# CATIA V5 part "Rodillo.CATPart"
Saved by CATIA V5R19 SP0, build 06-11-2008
Part number: Rodillo
Publications: "Plane.1"
Material "Iron": density 7870 kg/m3, Young's modulus 1.2e+11 Pa, Poisson ratio 0.291, thermal expansion 1.21e-05 1/K
Bounding box of the stored display mesh (mm): x -19.05 to 19.05, y -25.4 to 25.4, z -25.215 to 25.215
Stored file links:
  E:\Luis\Dropbox\3DIT\Parking\planos\cat 3 dit park8\Rodillo.CATPart
  E:\Luis\Dropbox\3DIT\Parking\planos\cat 3 dit park8\Eslabon de Cadena.........................................CATProduct
  E:\Luis\Dropbox\3DIT\Parking\planos\cat 3 dit park8\Pin Abierto.CATPart
  C:\Program Files (x86)\Dassault Systemes\B19\intel_a\startup\materials\Catalog.CATMaterial
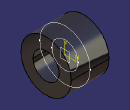
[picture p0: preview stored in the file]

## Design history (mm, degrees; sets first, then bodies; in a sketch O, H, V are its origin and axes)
Parameters
  d1 = 50.8
  d2 = 26.4
  b1 = 38.1
AxisSystem1: origin (0, 0, 0), X (1, 0, 0), Y (0, 1, 0), Z (0, 0, 1)
Set1
  Plane1: stored without definition
Set2
  Plane2: type Offset, Offset 0, RefPlane Plane1
Body1 (main body), material "Iron"
  Sketch1 on Plane1, origin (0, 0, 0), H (0, 1, 0), V (0, 0, 1)
    circle A1 centre (0, 0) radius 13.2
    circle A2 centre (0, 0) radius 25.4
    radius A2 = 25.4 {= d1 /2/1000}
    radius A1 = 13.2 {= d2 /2/1000}
  Pad1: profile Sketch1, direction (1, 0, 0), length 19.05 {= b1 /2/1000}, mirrored extent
